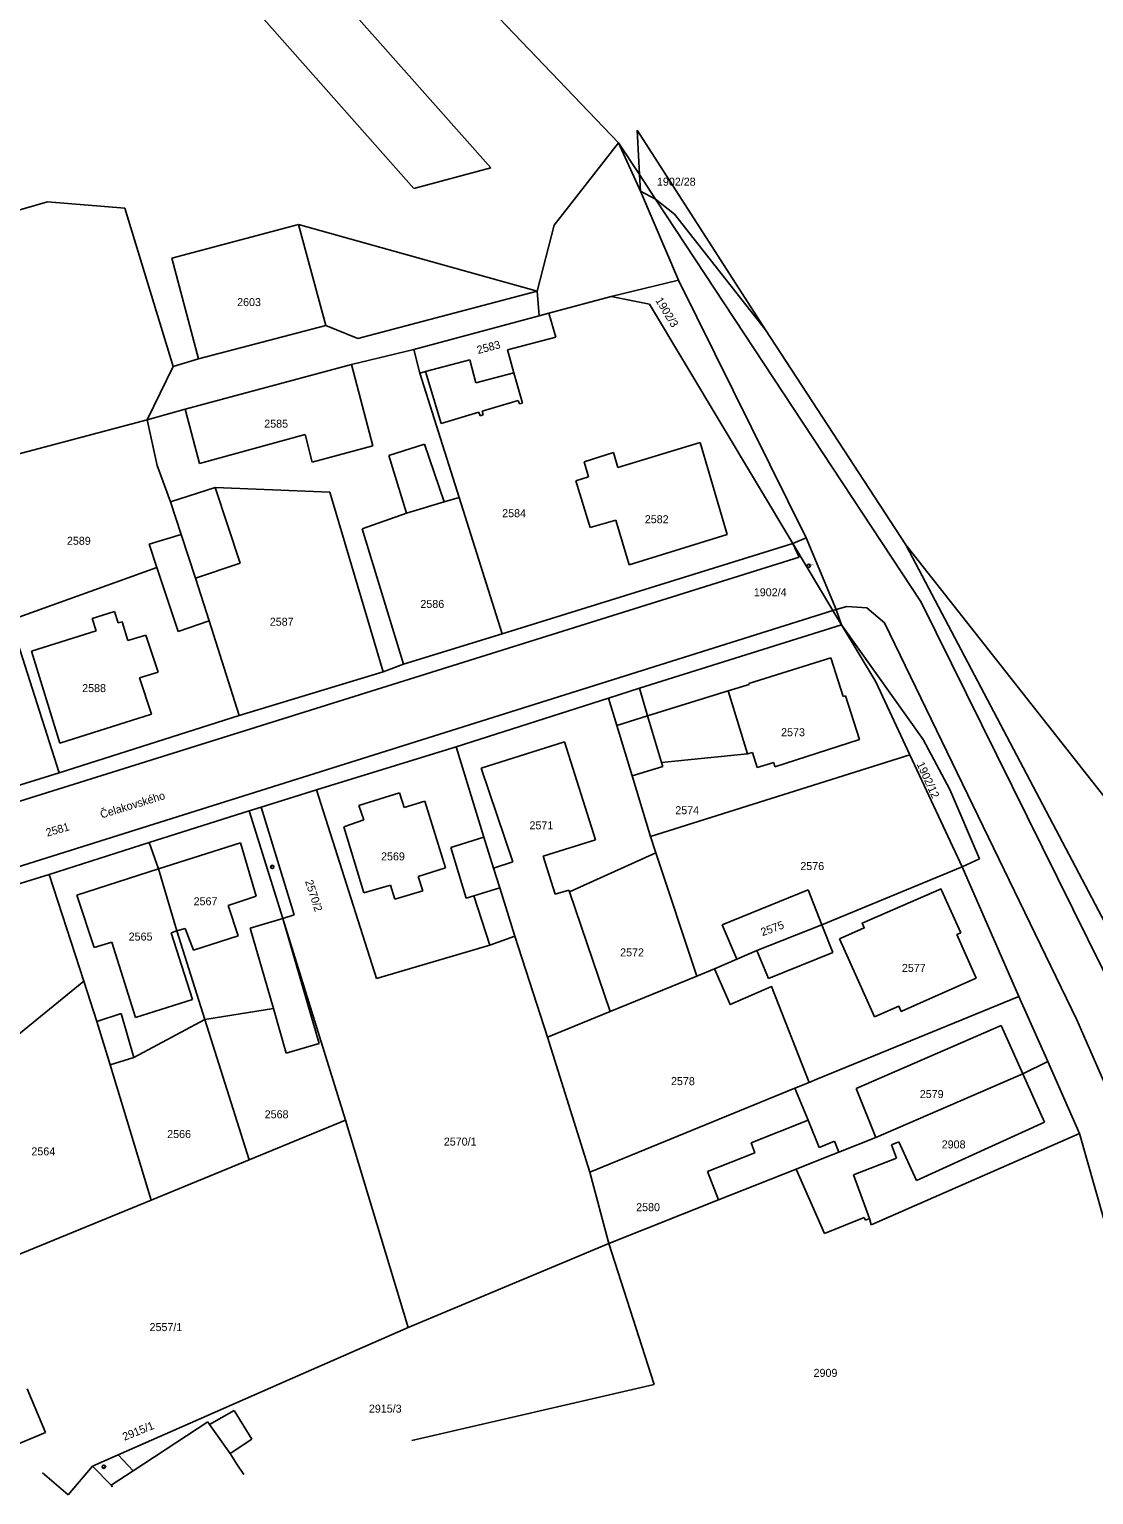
# Model space of a CAD drawing. Extents: x -722132 to -721608, y -1046877 to -1046449.
# Drawn here: x -722051.9 to -721938.8, y -1046876.3 to -1046720.6 of the extents above; entities that cross this region are included whole.
import ezdxf

# ---------------------------------------------------------------- set-up
doc = ezdxf.new("R2010")
doc.units = 0
for name, color, linetype in [('Vrstva 1', 7, 'Continuous'), ('Vrstva 15', 7, 'Continuous'), ('Vrstva 16', 7, 'Continuous'), ('Vrstva 18', 7, 'Continuous'), ('Vrstva 19', 7, 'Continuous'), ('Vrstva 4', 7, 'Continuous'), ('Vrstva 6', 7, 'Continuous')]:
    doc.layers.add(name, color=color, linetype=linetype)

msp = doc.modelspace()

# ---------------------------------------------------------------- linework, layer by layer
at = {"layer": 'Vrstva 1'}
for p, q in [((-721986.97, -1046737.78), (-721985.35, -1046738.64)), ((-721985.35, -1046738.64), (-721983.33, -1046740.22)), ((-722049.94, -1046738.91), (-722082, -1046748.2)), ((-721983.33, -1046740.22), (-721973.69, -1046752.53)), ((-722024.5, -1046864.15), (-722011.65, -1046858.5)), ((-722042.44, -1046872.03), (-722024.5, -1046864.15))]:
    msp.add_line(p, q, dxfattribs=at)
for points in [[(-722025.76, -1046694.5), (-721989.29, -1046732.65)], [(-722036.73, -1046697.11), (-722002.84, -1046735.3)], [(-722045.04, -1046699.09), (-722011.04, -1046737.52)], [(-722011.04, -1046737.52), (-722002.84, -1046735.3)], [(-722049.94, -1046738.91), (-722041.74, -1046739.6)], [(-722041.74, -1046739.6), (-722036.62, -1046756.41)], [(-722036.76, -1046744.91), (-722023.29, -1046741.33)], [(-722023.29, -1046741.33), (-722020.4, -1046752.06)], [(-722036.76, -1046744.91), (-722033.92, -1046755.62)], [(-721996.69, -1046750.76), (-721990.09, -1046748.98)], [(-721990.09, -1046748.98), (-721985.99, -1046749.78)], [(-722011.03, -1046754.61), (-721997.73, -1046751.04)], [(-721997.73, -1046751.04), (-721996.69, -1046750.76)], [(-721996.69, -1046750.76), (-721995.95, -1046753.29)], [(-721985.99, -1046749.78), (-721970.78, -1046775.23)], [(-722033.92, -1046755.62), (-722020.4, -1046752.06)], [(-721973.69, -1046752.53), (-721958.77, -1046775.35)], [(-722001.08, -1046754.65), (-721995.95, -1046753.29)], [(-722017.66, -1046756.21), (-722011.03, -1046754.61)], [(-722011.03, -1046754.61), (-722010.39, -1046757.12)], [(-722009.8, -1046756.94), (-722005.1, -1046755.71)], [(-722005.1, -1046755.71), (-722004.44, -1046758.14)], [(-722001.08, -1046754.65), (-722000.43, -1046757.08)], [(-722039.36, -1046762.1), (-722036.62, -1046756.41)], [(-722035.32, -1046760.95), (-722017.66, -1046756.21)], [(-722010.39, -1046757.12), (-722009.8, -1046756.94)], [(-722010.39, -1046757.12), (-722006.22, -1046770.33)], [(-722004.44, -1046758.14), (-722000.43, -1046757.08)], [(-722059.02, -1046767.28), (-722039.36, -1046762.1)], [(-722039.36, -1046762.1), (-722035.32, -1046760.95)], [(-722039.36, -1046762.1), (-722038.29, -1046766.95)], [(-721989.35, -1046767.15), (-721980.63, -1046764.5)], [(-721980.63, -1046764.5), (-721977.75, -1046774.27)], [(-721992.95, -1046766.53), (-721989.84, -1046765.54)], [(-721992.95, -1046766.53), (-721992.47, -1046768.15)], [(-721989.84, -1046765.54), (-721989.35, -1046767.15)], [(-722038.29, -1046766.95), (-722036.9, -1046770.79)], [(-721993.84, -1046768.55), (-721992.47, -1046768.15)], [(-722032.15, -1046769.26), (-722019.96, -1046769.78)], [(-722032.15, -1046769.26), (-722029.5, -1046777.31)], [(-722019.96, -1046769.78), (-722014.3, -1046788.85)], [(-721993.84, -1046768.55), (-721992.32, -1046773.51)], [(-722036.9, -1046770.79), (-722035.75, -1046774.28)], [(-722011.8, -1046772.01), (-722007.83, -1046770.78)], [(-722007.83, -1046770.78), (-722006.22, -1046770.33)], [(-722006.22, -1046770.33), (-722001.65, -1046784.81)], [(-722016.51, -1046773.65), (-722011.8, -1046772.01)], [(-721992.32, -1046773.51), (-721989.59, -1046772.73)], [(-721989.59, -1046772.73), (-721988.16, -1046777.49)], [(-722039.16, -1046775.31), (-722035.75, -1046774.28)], [(-722035.75, -1046774.28), (-722034.23, -1046778.91)], [(-722016.51, -1046773.65), (-722012.12, -1046788.06)], [(-721988.16, -1046777.49), (-721977.75, -1046774.27)], [(-722039.16, -1046775.31), (-722038.33, -1046777.78)], [(-722001.65, -1046784.81), (-721970.78, -1046775.23)], [(-721970.78, -1046775.23), (-721966.51, -1046782.33)], [(-721958.77, -1046775.35), (-721932.42, -1046825.36)], [(-721958.77, -1046775.35), (-721923, -1046820.76)], [(-722034.23, -1046778.91), (-722029.5, -1046777.31)], [(-722053.89, -1046783.38), (-722038.33, -1046777.78)], [(-722034.23, -1046778.91), (-722032.78, -1046783.45)], [(-721966.51, -1046782.33), (-721965.6, -1046783.88)], [(-722053.89, -1046783.38), (-722048.73, -1046799.58)], [(-722032.78, -1046783.45), (-722029.58, -1046793.48)], [(-721987.08, -1046790.61), (-721965.6, -1046783.88)], [(-721965.6, -1046783.88), (-721961.95, -1046789.92)], [(-722012.12, -1046788.06), (-722001.65, -1046784.81)], [(-722014.3, -1046788.85), (-722012.12, -1046788.06)], [(-721975.45, -1046790.09), (-721966.74, -1046787.36)], [(-721966.74, -1046787.36), (-721965.44, -1046791.48)], [(-722029.58, -1046793.48), (-722014.3, -1046788.85)], [(-721975.45, -1046790.09), (-721975.42, -1046790.19)], [(-721961.95, -1046789.92), (-721958.36, -1046797.66)], [(-722006.55, -1046796.81), (-721990.36, -1046791.65)], [(-721990.36, -1046791.65), (-721987.08, -1046790.61)], [(-721990.36, -1046791.65), (-721989.48, -1046794.55)], [(-721986.2, -1046793.54), (-721977.63, -1046790.89)], [(-721977.63, -1046790.89), (-721975.42, -1046790.19)], [(-721965.44, -1046791.48), (-721965.17, -1046791.4)], [(-721965.17, -1046791.4), (-721963.71, -1046796.05)], [(-722048.73, -1046799.58), (-722029.58, -1046793.48)], [(-721989.48, -1046794.55), (-721986.2, -1046793.54)], [(-721989.48, -1046794.55), (-721987.85, -1046799.89)], [(-721972.69, -1046798.94), (-721963.71, -1046796.05)], [(-722021.37, -1046801.41), (-722006.55, -1046796.81)], [(-722006.55, -1046796.81), (-722003.61, -1046806.44)], [(-721985.88, -1046806.37), (-721958.36, -1046797.66)], [(-721984.72, -1046798.48), (-721975.6, -1046797.58)], [(-721975.6, -1046797.58), (-721975.07, -1046797.42)], [(-721975.07, -1046797.42), (-721974.58, -1046799.02)], [(-721958.36, -1046797.66), (-721952.79, -1046809.56)], [(-721987.85, -1046799.89), (-721984.59, -1046798.9)], [(-721984.72, -1046798.48), (-721984.59, -1046798.9)], [(-721974.58, -1046799.02), (-721972.81, -1046798.5)], [(-721972.81, -1046798.5), (-721972.69, -1046798.94)], [(-722063.49, -1046804.15), (-722048.73, -1046799.58)], [(-721987.85, -1046799.89), (-721985.88, -1046806.37)], [(-722027.25, -1046803.23), (-722021.37, -1046801.41)], [(-722021.37, -1046801.41), (-722014.99, -1046821.45)], [(-722039.15, -1046807), (-722028.53, -1046803.63)], [(-722028.53, -1046803.63), (-722027.25, -1046803.23)], [(-722028.53, -1046803.63), (-722024.97, -1046815.05)], [(-722027.25, -1046803.23), (-722023.76, -1046814.69)], [(-722049.78, -1046810.38), (-722039.15, -1046807)], [(-722039.15, -1046807), (-722038.15, -1046809.79)], [(-722003.61, -1046806.44), (-722002.56, -1046809.72)], [(-721985.88, -1046806.37), (-721985.32, -1046808.08)], [(-721994.51, -1046812.24), (-721985.32, -1046808.08)], [(-721985.32, -1046808.08), (-721980.97, -1046821.2)], [(-722038.15, -1046809.79), (-722036.2, -1046816.38)], [(-722002.56, -1046809.72), (-722001.9, -1046811.8)], [(-721967.68, -1046815.73), (-721952.79, -1046809.56)], [(-721952.79, -1046809.56), (-721946.77, -1046823.35)], [(-722065.97, -1046815.38), (-722049.78, -1046810.38)], [(-722049.78, -1046810.38), (-722046.09, -1046821.73)], [(-722001.9, -1046811.8), (-722000.3, -1046816.94)], [(-721994.51, -1046812.24), (-721990.18, -1046824.95)], [(-721978.27, -1046815.73), (-721969.14, -1046812.03)], [(-721969.14, -1046812.03), (-721967.68, -1046815.73)], [(-722024.97, -1046815.05), (-722023.76, -1046814.69)], [(-722036.2, -1046816.38), (-722033.23, -1046825.79)], [(-722024.97, -1046815.05), (-722021.08, -1046828.35)], [(-722024.97, -1046815.05), (-722018.31, -1046836.48)], [(-721978.27, -1046815.73), (-721976.73, -1046819.4)], [(-721974.6, -1046818.46), (-721967.68, -1046815.73)], [(-722014.99, -1046821.45), (-722002.98, -1046817.89)], [(-722002.98, -1046817.89), (-722000.3, -1046816.94)], [(-722000.3, -1046816.94), (-721996.85, -1046827.67)], [(-721979.09, -1046820.4), (-721976.73, -1046819.4)], [(-721976.73, -1046819.4), (-721974.6, -1046818.46)], [(-721990.18, -1046824.95), (-721980.97, -1046821.2)], [(-721980.97, -1046821.2), (-721979.09, -1046820.4)], [(-721979.09, -1046820.4), (-721977.45, -1046824.21), (-721973.04, -1046822.29), (-721969.05, -1046832.48)], [(-722057.45, -1046830.97), (-722046.09, -1046821.73)], [(-722046.09, -1046821.73), (-722044.71, -1046825.99)], [(-721968.22, -1046832.14), (-721946.77, -1046823.35)], [(-721946.77, -1046823.35), (-721943.69, -1046830.24)], [(-722040.77, -1046829.82), (-722033.23, -1046825.79)], [(-722033.23, -1046825.79), (-722025.96, -1046824.63)], [(-722033.23, -1046825.79), (-722028.53, -1046840.72)], [(-722025.96, -1046824.63), (-722024.59, -1046829.37)], [(-721996.85, -1046827.67), (-721990.18, -1046824.95)], [(-722044.71, -1046825.99), (-722043.31, -1046830.6)], [(-722024.59, -1046829.37), (-722021.08, -1046828.35)], [(-721996.85, -1046827.67), (-721992.35, -1046842.02)], [(-722043.31, -1046830.6), (-722040.77, -1046829.82)], [(-722043.31, -1046830.6), (-722038.94, -1046844.98)], [(-721946.34, -1046831.56), (-721943.69, -1046830.24)], [(-721943.69, -1046830.24), (-721940.32, -1046837.92)], [(-721969.05, -1046832.48), (-721968.22, -1046832.14)], [(-721961.96, -1046838.32), (-721946.34, -1046831.56)], [(-721992.35, -1046842.02), (-721970.58, -1046833.1)], [(-721970.58, -1046833.1), (-721969.05, -1046832.48)], [(-721970.58, -1046833.1), (-721969.13, -1046836.5)], [(-722028.53, -1046840.72), (-722018.31, -1046836.48)], [(-722018.31, -1046836.48), (-722011.65, -1046858.5)], [(-721975.22, -1046838.91), (-721969.13, -1046836.5)], [(-721965.89, -1046839.88), (-721961.96, -1046838.32)], [(-721962.46, -1046847.6), (-721940.32, -1046837.92)], [(-721940.32, -1046837.92), (-721936.19, -1046852.5)], [(-721975.22, -1046838.91), (-721974.8, -1046839.96)], [(-721967.52, -1046840.53), (-721965.89, -1046839.88)], [(-722038.94, -1046844.98), (-722028.53, -1046840.72)], [(-721979.85, -1046841.96), (-721974.8, -1046839.96)], [(-721970.43, -1046841.68), (-721967.52, -1046840.53)], [(-721992.35, -1046842.02), (-721990.33, -1046849.58)], [(-721979.85, -1046841.96), (-721978.66, -1046844.95)], [(-721978.66, -1046844.95), (-721970.43, -1046841.68)], [(-721970.43, -1046841.68), (-721967.41, -1046848.54)], [(-722054.73, -1046851.47), (-722038.94, -1046844.98)], [(-721990.33, -1046849.58), (-721978.66, -1046844.95)], [(-721967.41, -1046848.54), (-721963.19, -1046846.82)], [(-721963.19, -1046846.82), (-721963.07, -1046847.12)], [(-721963.07, -1046847.12), (-721962.63, -1046846.94)], [(-721962.63, -1046846.94), (-721962.46, -1046847.6)], [(-722011.65, -1046858.5), (-721990.33, -1046849.58)], [(-721990.33, -1046849.58), (-721985.5, -1046864.57)], [(-722052.12, -1046865.02), (-722050.17, -1046869.67)], [(-722032.75, -1046868.81), (-722030.14, -1046867.33)], [(-722030.14, -1046867.33), (-722028.23, -1046870.39)], [(-722040.85, -1046873.74), (-722032.91, -1046868.54)], [(-722032.91, -1046868.54), (-722032.75, -1046868.81)], [(-722053.89, -1046871.23), (-722050.17, -1046869.67)], [(-722030.55, -1046871.91), (-722028.23, -1046870.39)], [(-722045.19, -1046873.24), (-722042.44, -1046872.03)], [(-722030.55, -1046871.91), (-722029.83, -1046873.02)], [(-722050.49, -1046873.97), (-722047.77, -1046876.28)], [(-722047.77, -1046876.28), (-722045.19, -1046873.24)], [(-722045.19, -1046873.24), (-722043.18, -1046875.27)], [(-722043.18, -1046875.27), (-722040.85, -1046873.74)], [(-722029.83, -1046873.02), (-722029.1, -1046874.15)], [(-722043.18, -1046875.27), (-722043.06, -1046875.45)]]:
    msp.add_lwpolyline(points, dxfattribs=at)
at = {"layer": 'Vrstva 16'}
for points in [[(-721969.01, -1046777.54), (-721969.08, -1046777.59)], [(-722026.25, -1046809.55), (-722026.08, -1046809.59)], [(-722043.98, -1046873.34), (-722043.97, -1046873.31)]]:
    msp.add_lwpolyline(points, dxfattribs=at)
for centre in [(-721969.08, -1046777.59), (-722026.08, -1046809.59), (-722043.97, -1046873.31)]:
    msp.add_circle(centre, 0.175, dxfattribs=at)
at = {"layer": 'Vrstva 4'}
for points in [[(-721996.13, -1046741.41), (-721989.29, -1046732.65)], [(-721989.29, -1046732.65), (-721987.06, -1046736.03)], [(-721987.06, -1046736.03), (-721985.35, -1046738.64)], [(-721985.35, -1046738.64), (-721957.14, -1046781.47)], [(-722023.29, -1046741.33), (-721997.94, -1046748.43)], [(-721997.94, -1046748.43), (-721996.13, -1046741.41)], [(-722016.98, -1046753.45), (-721997.94, -1046748.43)], [(-721997.94, -1046748.43), (-721997.73, -1046751.04)], [(-722020.4, -1046752.06), (-722016.98, -1046753.45)], [(-722036.62, -1046756.41), (-722033.92, -1046755.62)], [(-722017.66, -1046756.21), (-722015.38, -1046764.83)], [(-722009.8, -1046756.94), (-722008.15, -1046762.47)], [(-722000.43, -1046757.08), (-721999.49, -1046760.31)], [(-722003.78, -1046761.18), (-721999.96, -1046760.02)], [(-721999.96, -1046760.02), (-721999.82, -1046760.4)], [(-721999.82, -1046760.4), (-721999.49, -1046760.31)], [(-722035.32, -1046760.95), (-722033.79, -1046766.72)], [(-722008.15, -1046762.47), (-722004.12, -1046761.27)], [(-722004.12, -1046761.27), (-722004, -1046761.66)], [(-722004, -1046761.66), (-722003.68, -1046761.55)], [(-722003.78, -1046761.18), (-722003.68, -1046761.55)], [(-722033.79, -1046766.72), (-722022.58, -1046763.66)], [(-722022.58, -1046763.66), (-722021.82, -1046766.58)], [(-722021.82, -1046766.58), (-722015.38, -1046764.83)], [(-722013.68, -1046765.87), (-722009.91, -1046764.68)], [(-722009.91, -1046764.68), (-722007.83, -1046770.78)], [(-722013.68, -1046765.87), (-722011.8, -1046772.01)], [(-722036.9, -1046770.79), (-722032.15, -1046769.26)], [(-721970.78, -1046775.23), (-721970.1, -1046776.68)], [(-722062.88, -1046805.71), (-721970.1, -1046776.68)], [(-722038.33, -1046777.78), (-722036.06, -1046784.58)], [(-722060.86, -1046812.01), (-721966.51, -1046782.33)], [(-721966.51, -1046782.33), (-721966.17, -1046782.23)], [(-721966.17, -1046782.23), (-721965.04, -1046781.9)], [(-721965.04, -1046781.9), (-721962.93, -1046782.06)], [(-721962.93, -1046782.06), (-721961.03, -1046783.66)], [(-721957.14, -1046781.47), (-721936.21, -1046823.76)], [(-722045.21, -1046783.19), (-722042.82, -1046782.44)], [(-722045.21, -1046783.19), (-722044.8, -1046784.51)], [(-722042.82, -1046782.44), (-722042.45, -1046783.66)], [(-722042.45, -1046783.66), (-722042.01, -1046783.53)], [(-722042.01, -1046783.53), (-722041.41, -1046785.53)], [(-722036.06, -1046784.58), (-722032.78, -1046783.45)], [(-721961.03, -1046783.66), (-721940.59, -1046825.83)], [(-722051.65, -1046786.65), (-722044.8, -1046784.51)], [(-722041.41, -1046785.53), (-722039.49, -1046784.95)], [(-722039.49, -1046784.95), (-722038.2, -1046788.9)], [(-722051.65, -1046786.65), (-722048.65, -1046796.42)], [(-722040.17, -1046789.5), (-722038.2, -1046788.9)], [(-722040.17, -1046789.5), (-722038.91, -1046793.34)], [(-721987.08, -1046790.61), (-721986.2, -1046793.54)], [(-721977.63, -1046790.89), (-721975.6, -1046797.58)], [(-722048.65, -1046796.42), (-722038.91, -1046793.34)], [(-721986.2, -1046793.54), (-721984.72, -1046798.48)], [(-722003.9, -1046799.09), (-721995.04, -1046796.29)], [(-721995.04, -1046796.29), (-721991.74, -1046806.7)], [(-722003.9, -1046799.09), (-722000.52, -1046809.03)], [(-722016.87, -1046803.06), (-722012.56, -1046801.73)], [(-722012.56, -1046801.73), (-722012.08, -1046803.27)], [(-722016.87, -1046803.06), (-722016.35, -1046804.58)], [(-722012.08, -1046803.27), (-722009.88, -1046802.59)], [(-722009.88, -1046802.59), (-722007.68, -1046809.68)], [(-722018.49, -1046805.32), (-722016.35, -1046804.58)], [(-722018.49, -1046805.32), (-722016.34, -1046812.35)], [(-722038.15, -1046809.79), (-722029.46, -1046807.02)], [(-722029.46, -1046807.02), (-722027.8, -1046812.69)], [(-722007.1, -1046807.52), (-722003.61, -1046806.44)], [(-721997.3, -1046808.44), (-721991.74, -1046806.7)], [(-722007.1, -1046807.52), (-722005.49, -1046812.92)], [(-721997.3, -1046808.44), (-721996.02, -1046812.49)], [(-722046.84, -1046812.57), (-722038.15, -1046809.79)], [(-722010.57, -1046810.61), (-722007.68, -1046809.68)], [(-722002.56, -1046809.72), (-722000.52, -1046809.03)], [(-722016.34, -1046812.35), (-722013.5, -1046811.53)], [(-722013.5, -1046811.53), (-722013.07, -1046813.02)], [(-722010.57, -1046810.61), (-722010.08, -1046812.13)], [(-722004.68, -1046812.67), (-722001.9, -1046811.8)], [(-722046.84, -1046812.57), (-722044.98, -1046818.14)], [(-722030.77, -1046813.68), (-722027.8, -1046812.69)], [(-722013.07, -1046813.02), (-722010.08, -1046812.13)], [(-722005.49, -1046812.92), (-722004.68, -1046812.67)], [(-722004.68, -1046812.67), (-722002.98, -1046817.89)], [(-721996.02, -1046812.49), (-721994.57, -1046812.06)], [(-721994.57, -1046812.06), (-721994.51, -1046812.24)], [(-721954.97, -1046812.06), (-721955.03, -1046811.93), (-721963.41, -1046815.55), (-721963.19, -1046816.07), (-721965.81, -1046817.24)], [(-721954.97, -1046812.06), (-721952.94, -1046816.59)], [(-722030.77, -1046813.68), (-722029.71, -1046816.92)], [(-722036.81, -1046816.57), (-722036.2, -1046816.38)], [(-722036.81, -1046816.57), (-722034.56, -1046823.66)], [(-722036.2, -1046816.38), (-722035.33, -1046816.11)], [(-722035.33, -1046816.11), (-722034.46, -1046818.44)], [(-722028.44, -1046816.08), (-722024.97, -1046815.05)], [(-722028.44, -1046816.08), (-722025.96, -1046824.63)], [(-721967.68, -1046815.73), (-721966.54, -1046818.66)], [(-721953.37, -1046816.78), (-721952.94, -1046816.59)], [(-722044.98, -1046818.14), (-722043.12, -1046817.59)], [(-722043.12, -1046817.59), (-722040.6, -1046825.57)], [(-722034.46, -1046818.44), (-722029.71, -1046816.92)], [(-721965.81, -1046817.24), (-721962.1, -1046825.51), (-721959.5, -1046824.38), (-721959.26, -1046824.93), (-721959.13, -1046824.87)], [(-721953.37, -1046816.78), (-721951.29, -1046821.42)], [(-721974.6, -1046818.46), (-721973.37, -1046821.44)], [(-721973.37, -1046821.44), (-721966.54, -1046818.66)], [(-721959.13, -1046824.87), (-721951.29, -1046821.42)], [(-722040.6, -1046825.57), (-722034.56, -1046823.66)], [(-722044.71, -1046825.99), (-722042.13, -1046825.17)], [(-722042.13, -1046825.17), (-722040.77, -1046829.82)], [(-721940.59, -1046825.83), (-721934.9, -1046838.85)], [(-721964.04, -1046833.11), (-721948.66, -1046826.43)], [(-721948.66, -1046826.43), (-721946.34, -1046831.56)], [(-721946.34, -1046831.56), (-721944.03, -1046836.69)], [(-721964.04, -1046833.11), (-721961.96, -1046838.32)], [(-721969.13, -1046836.5), (-721967.98, -1046839.38)], [(-721957.65, -1046842.89), (-721944.03, -1046836.69)], [(-721967.98, -1046839.38), (-721966.35, -1046838.73)], [(-721966.35, -1046838.73), (-721965.89, -1046839.88)], [(-721960.31, -1046839.12), (-721959.51, -1046838.79)], [(-721960.31, -1046839.12), (-721959.75, -1046840.52)], [(-721959.51, -1046838.79), (-721957.65, -1046842.89)], [(-721964.32, -1046842.3), (-721959.75, -1046840.52)], [(-721964.32, -1046842.3), (-721962.63, -1046846.94)], [(-722032.75, -1046868.81), (-722030.55, -1046871.91)]]:
    msp.add_lwpolyline(points, dxfattribs=at)
at = {"layer": 'Vrstva 6'}
for points in [[(-721987.32, -1046731.31), (-721973.69, -1046752.53)], [(-721987.32, -1046731.31), (-721987.06, -1046736.03)], [(-721989.29, -1046732.65), (-721986.97, -1046737.78)], [(-721987.06, -1046736.03), (-721986.97, -1046737.78)], [(-721986.97, -1046737.78), (-721982.93, -1046747.23)], [(-721990.09, -1046748.98), (-721982.93, -1046747.23)], [(-721982.93, -1046747.23), (-721969.35, -1046774.62)], [(-721970.78, -1046775.23), (-721969.35, -1046774.62)], [(-721969.35, -1046774.62), (-721966.17, -1046782.23)], [(-721966.17, -1046782.23), (-721965.6, -1046783.88)], [(-721965.6, -1046783.88), (-721956.93, -1046796.06)], [(-721956.93, -1046796.06), (-721954.11, -1046801.36)], [(-721954.11, -1046801.36), (-721950.93, -1046808.73)], [(-721952.79, -1046809.56), (-721950.93, -1046808.73)], [(-722011.26, -1046870.54), (-721985.5, -1046864.57)], [(-722042.44, -1046872.03), (-722040.85, -1046873.74)]]:
    msp.add_lwpolyline(points, dxfattribs=at)

# ---------------------------------------------------------------- texts
at = {"layer": 'Vrstva 15'}
msp.add_text('Čelakovského', height=0.85, rotation=17.0288, dxfattribs=at).set_placement((-722044.21, -1046804.44))
at = {"layer": 'Vrstva 16'}
msp.add_text('1902/4', height=0.85, dxfattribs=at).set_placement((-721974.92, -1046780.83))
for s, rotation, p in [('2570/2', 288.0272, (-722022.6, -1046811.12)), ('2915/1', 21.923, (-722041.78, -1046870.56))]:
    msp.add_text(s, height=0.85, rotation=rotation, dxfattribs=at).set_placement(p)
at = {"layer": 'Vrstva 18'}
for s, height, p in [('1902/28', 0.85, (-721985.21, -1046737.21)), ('2584', 0.85, (-722001.65, -1046772.43)), ('2589', 0.85, (-722047.89, -1046775.36)), ('1902/4', 0.1, (-721969.01, -1046777.54)), ('2586', 0.85, (-722010.34, -1046782.07)), ('2587', 0.85, (-722026.34, -1046783.96)), ('2574', 0.85, (-721983.26, -1046803.98)), ('2576', 0.85, (-721969.98, -1046809.92)), ('2572', 0.85, (-721989.12, -1046819.09)), ('2578', 0.85, (-721983.72, -1046832.77)), ('2568', 0.85, (-722026.88, -1046836.29)), ('2566', 0.85, (-722037.24, -1046838.39)), ('2570/1', 0.85, (-722007.85, -1046839.19)), ('2564', 0.85, (-722051.66, -1046840.23)), ('2580', 0.85, (-721987.42, -1046846.16)), ('2557/1', 0.85, (-722039.11, -1046858.9)), ('2909', 0.85, (-721968.57, -1046863.76)), ('2915/3', 0.85, (-722015.81, -1046867.56)), ('2915/1', 0.1, (-722043.98, -1046873.34))]:
    msp.add_text(s, height=height, dxfattribs=at).set_placement(p)
for s, height, rotation, p in [('1902/3', 0.85, 301.3927, (-721985.41, -1046749.39)), ('1902/12', 0.85, 294.604, (-721957.65, -1046798.65)), ('2581', 0.85, 16.2238, (-722049.98, -1046806.38)), ('2570/2', 0.1, 359.3547, (-722026.25, -1046809.55))]:
    msp.add_text(s, height=height, rotation=rotation, dxfattribs=at).set_placement(p)
at = {"layer": 'Vrstva 19'}
for s, p in [('2603', (-722029.81, -1046750)), ('2585', (-722026.93, -1046762.92)), ('2582', (-721986.5, -1046773.07)), ('2588', (-722046.27, -1046791.01)), ('2573', (-721972.02, -1046795.7)), ('2571', (-721998.75, -1046805.59)), ('2569', (-722014.52, -1046808.89)), ('2567', (-722034.43, -1046813.66)), ('2565', (-722041.33, -1046817.41)), ('2577', (-721959.19, -1046820.74)), ('2579', (-721957.29, -1046834.14)), ('2908', (-721954.96, -1046839.49))]:
    msp.add_text(s, height=0.85, dxfattribs=at).set_placement(p)
for s, rotation, p in [('2583', 14.8333, (-722004.21, -1046755.1)), ('2575', 20.0575, (-721974, -1046816.95))]:
    msp.add_text(s, height=0.85, rotation=rotation, dxfattribs=at).set_placement(p)

doc.saveas('drawing.dxf')
